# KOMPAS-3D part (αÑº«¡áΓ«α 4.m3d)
File: created 06.04.2016 12:01:11, last saved 07.04.2016 18:26:25.
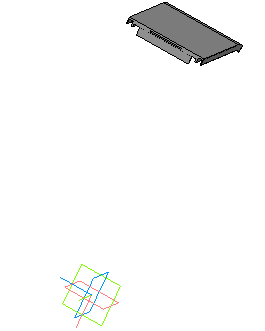
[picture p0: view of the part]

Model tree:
1. Эскиз:1
2. Операция выдавливания:1
     Толщина стенки 1 = 2; Толщина стенки 2 = 6; Расстояние 1 = 1
3. Эскиз:2
4. Операция выдавливания:2
     Толщина стенки 1 = 2; Толщина стенки 2 = 7; Расстояние 1 = 5
5. Эскиз:3
6. Операция выдавливания:3
     Толщина стенки 1 = 2; Толщина стенки 2 = 6; Расстояние 1 = 2
7. Эскиз:4
8. Операция выдавливания:4
     Толщина стенки 1 = 2; Толщина стенки 2 = 2.5; Расстояние 1 = 60
9. Эскиз:5
10. Вырезать элемент выдавливания:1
     Толщина стенки 2 = 1.5; Расстояние 1 = 40
11. Эскиз:6
12. Операция выдавливания:5
     Толщина стенки 1 = 2; Толщина стенки 2 = 2.5; Расстояние 1 = 20
13. Эскиз:7
14. Операция выдавливания:6
     Толщина стенки 1 = 2; Толщина стенки 2 = 6; Расстояние 1 = 2
15. Эскиз:8
16. Операция выдавливания:7
     Толщина стенки 1 = 2; Толщина стенки 2 = 6; Расстояние 1 = 5
17. Эскиз:9
18. Операция выдавливания:8
     Толщина стенки 1 = 2; Толщина стенки 2 = 6; Расстояние 1 = 1
19. Эскиз:10
20. Вырезать элемент выдавливания:2
     Толщина стенки 2 = 1.5; Расстояние 1 = 22
21. Эскиз:11
22. Вырезать элемент выдавливания:3
     Толщина стенки 2 = 1.5; Расстояние 1 = 1
23. Скругление:4
     Радиус = 1
24. Эскиз:12
25. Вырезать элемент выдавливания:4
     Расстояние 1 = 100
26. Эскиз:13
27. Операция выдавливания:9
     Толщина стенки 1 = 6; Толщина стенки 2 = 9.5; Расстояние 1 = 60; Расстояние 2 = 0.4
